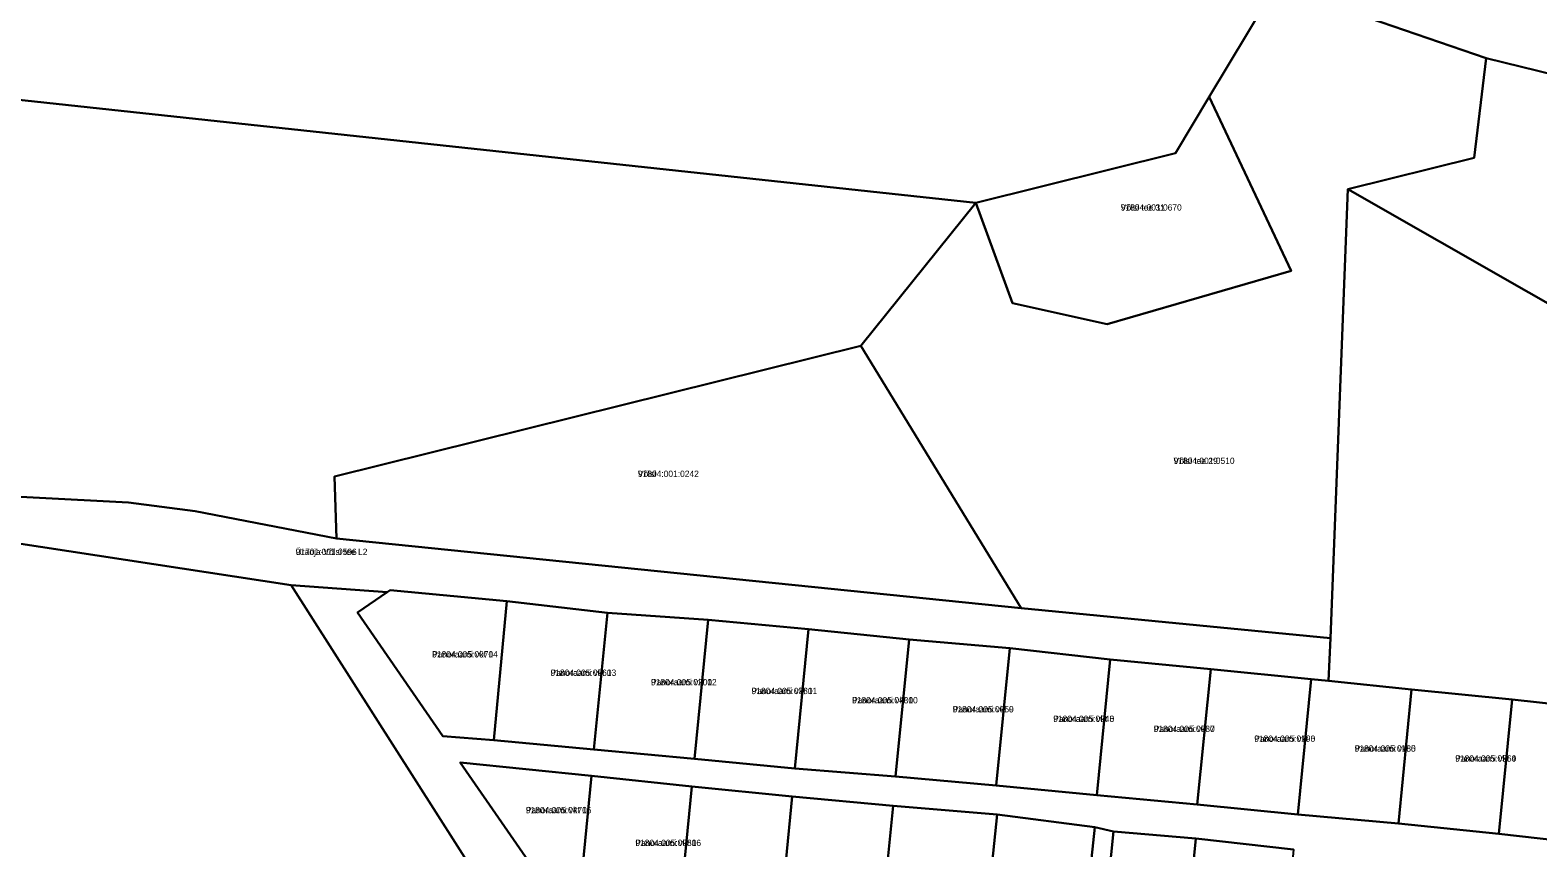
# Model space of a CAD drawing. Extents: x 655954 to 711923, y 6395079 to 6429745.
# Drawn here: x 676838.5 to 677196.9, y 6413724.6 to 6413918.9 of the extents above; entities that cross this region are included whole.
import ezdxf

# ---------------------------------------------------------------- set-up
doc = ezdxf.new("R2010")
doc.units = 0
for name, color, linetype in [('L_AADRESS', 7, 'Continuous'), ('PIIR', 7, 'Continuous'), ('TUNNUS', 7, 'Continuous')]:
    doc.layers.add(name, color=color, linetype=linetype)

msp = doc.modelspace()

# ---------------------------------------------------------------- linework, layer by layer
at = {"layer": 'PIIR'}
for points in [[(676618.85, 6413997.29), (676757.83, 6413982), (676748.25, 6413911.76), (677063.36, 6413877.89), (677036.02, 6413843.93), (676910.92, 6413812.85), (676911.36, 6413798.1), (676877.79, 6413804.6), (676861.95, 6413806.69), (676815, 6413809.12), (676760.41, 6413820.5), (676743.02, 6413822.9), (676724.12, 6413824.15), (676460.26, 6413781.02), (676439.86, 6413783.73), (676405.75, 6413788.28), (676399, 6413875.26), (676597.13, 6413862.25)], [(676757.83, 6413982), (676917.87, 6413963.45), (676991.22, 6413952.53), (677063.97, 6413940.17), (677132.61, 6413926), (677118.76, 6413903.06), (677110.76, 6413889.72), (677063.36, 6413877.89), (676748.25, 6413911.76)], [(677036.02, 6413843.93), (677063.36, 6413877.89), (677072.07, 6413854.02), (677094.58, 6413849.01), (677138.24, 6413861.74), (677118.76, 6413903.06), (677132.61, 6413926), (677134.69, 6413929.44), (677184.63, 6413912.26), (677181.78, 6413888.58), (677151.77, 6413881.11), (677147.6, 6413774.45), (677074.08, 6413781.56)], [(677151.77, 6413881.11), (677181.78, 6413888.58), (677184.63, 6413912.26), (677337.11, 6413874.84), (677343.16, 6413826.22), (677265.51, 6413773.16), (677238.84, 6413754.97), (677281.36, 6413807.1)], [(677063.36, 6413877.89), (677110.76, 6413889.72), (677118.76, 6413903.06), (677138.24, 6413861.74), (677094.58, 6413849.01), (677072.07, 6413854.02)], [(677147.6, 6413774.45), (677151.77, 6413881.11), (677281.36, 6413807.1), (677265.51, 6413773.16), (677256.27, 6413753.42), (677238.84, 6413754.97), (677214.64, 6413757.24), (677190.78, 6413759.81), (677166.9, 6413762.19), (677147.13, 6413764.24)], [(676910.92, 6413812.85), (677036.02, 6413843.93), (677074.08, 6413781.56), (676911.36, 6413798.1)], [(677147.6, 6413774.45), (677147.13, 6413764.24), (677143.03, 6413764.67), (677119.15, 6413767.07), (677095.25, 6413769.36), (677071.4, 6413772.06), (677047.47, 6413774.08), (677023.59, 6413776.53), (676999.69, 6413778.77), (676975.74, 6413780.46), (676951.83, 6413783.23), (676924.1, 6413785.82), (676923.38, 6413785.33), (676900.55, 6413787.01), (676722.83, 6413814.18), (676724.12, 6413824.15), (676743.02, 6413822.9), (676760.41, 6413820.5), (676815, 6413809.12), (676861.95, 6413806.69), (676877.79, 6413804.6), (676911.36, 6413798.1), (677074.08, 6413781.56)], [(676916.36, 6413780.5), (676923.38, 6413785.33), (676924.1, 6413785.82), (676951.83, 6413783.23), (676948.74, 6413750.14), (676936.62, 6413751.12)], [(676951.83, 6413783.23), (676975.74, 6413780.46), (676972.56, 6413747.96), (676948.74, 6413750.14)], [(676975.74, 6413780.46), (676999.69, 6413778.77), (676996.44, 6413745.72), (676972.56, 6413747.96)], [(676999.69, 6413778.77), (677023.59, 6413776.53), (677020.34, 6413743.47), (676996.44, 6413745.72)], [(677023.59, 6413776.53), (677047.47, 6413774.08), (677044.26, 6413741.54), (677020.34, 6413743.47)], [(677047.47, 6413774.08), (677071.4, 6413772.06), (677068.19, 6413739.43), (677044.26, 6413741.54)], [(677071.4, 6413772.06), (677095.25, 6413769.36), (677092.07, 6413737.13), (677068.19, 6413739.43)], [(677095.25, 6413769.36), (677119.15, 6413767.07), (677115.97, 6413734.87), (677092.07, 6413737.13)], [(677119.15, 6413767.07), (677143.03, 6413764.67), (677139.85, 6413732.51), (677115.97, 6413734.87)], [(677143.03, 6413764.67), (677147.13, 6413764.24), (677166.9, 6413762.19), (677163.76, 6413730.39), (677139.85, 6413732.51)], [(677166.9, 6413762.19), (677190.78, 6413759.81), (677187.63, 6413727.94), (677163.76, 6413730.39)], [(677190.78, 6413759.81), (677214.64, 6413757.24), (677211.48, 6413725.25), (677187.63, 6413727.94)], [(676963.98, 6413711.35), (676940.74, 6413744.84), (676971.97, 6413741.71), (676968.95, 6413710.82)], [(676968.95, 6413710.82), (676971.97, 6413741.71), (676995.85, 6413739.2), (676992.82, 6413708.35), (676985.56, 6413709.1)], [(676995.85, 6413739.2), (677019.7, 6413736.8), (677016.69, 6413705.72), (677001.51, 6413707.46), (676992.82, 6413708.35)], [(677040.59, 6413703.7), (677036.44, 6413704.17), (677018.82, 6413705.46), (677016.69, 6413705.72), (677019.7, 6413736.8), (677043.7, 6413734.54)], [(677043.7, 6413734.54), (677068.41, 6413732.49), (677065.16, 6413701.16), (677088.34, 6413698.99), (677076.26, 6413686.33), (677061.68, 6413701.52), (677040.59, 6413703.7)], [(677068.41, 6413732.49), (677091.65, 6413729.52), (677088.34, 6413698.99), (677065.16, 6413701.16)], [(677096.04, 6413728.43), (677092.88, 6413697.28), (677074.94, 6413677.09), (677075.6, 6413673.91), (677071.54, 6413668.9), (677053, 6413664.75), (677030.45, 6413659.62), (677007.01, 6413654.46), (676983.1, 6413649.39), (676959.15, 6413644.23), (676935.79, 6413639.38), (676913.44, 6413634.36), (676913.57, 6413640.66), (676950.06, 6413648.7), (676965.05, 6413651.99), (676981.14, 6413655.65), (676996.43, 6413659.58), (677012.12, 6413662.7), (677027.37, 6413665.74), (677043.95, 6413669.78), (677065.56, 6413675.12), (677076.26, 6413686.33), (677088.34, 6413698.99), (677091.65, 6413729.52)], [(677092.88, 6413697.28), (677096.04, 6413728.43), (677115.64, 6413726.84), (677112.86, 6413698.56), (677101.48, 6413690.21), (677102.75, 6413683.33), (677074.94, 6413677.09)], [(677112.88, 6413695.51), (677112.51, 6413685.52), (677102.75, 6413683.33), (677101.48, 6413690.21), (677112.86, 6413698.56), (677115.64, 6413726.84), (677138.84, 6413724.17), (677135.97, 6413693.58)]]:
    msp.add_lwpolyline(points, close=True, dxfattribs=at)
for points in [[(677789.14, 6413728.46), (677665.34, 6413764.41), (677639.35, 6413771.93), (677641.1, 6413778.01), (677587.87, 6413793.7), (677397.23, 6413855.41), (677337.11, 6413874.84), (677184.63, 6413912.26), (677134.69, 6413929.44), (677132.61, 6413926), (677063.97, 6413940.17), (676991.22, 6413952.53), (676917.87, 6413963.45), (676757.83, 6413982)], [(676722.83, 6413814.18), (676900.55, 6413787.01), (676949.83, 6413709.71), (676897.23, 6413654.7), (676920.56, 6413597.36), (676933.05, 6413555.27), (676946.82, 6413513.73), (676956.91, 6413480.43), (677002.62, 6413329.06), (677066.33, 6413319.15), (677231.27, 6413342.1), (677307.23, 6413354.1), (677309.72, 6413343.84), (677384.24, 6413366.61), (677380.25, 6413324.84), (677459.83, 6413354.2), (677597.5, 6413335.31), (677731.86, 6413311.49), (678085.04, 6413297.98), (678099.28, 6413215.93), (678143.84, 6412925.74)], [(676949.83, 6413709.71), (676900.55, 6413787.01), (676923.38, 6413785.33), (676916.36, 6413780.5), (676936.62, 6413751.12), (676948.74, 6413750.14), (676972.56, 6413747.96), (676996.44, 6413745.72), (677020.34, 6413743.47), (677044.26, 6413741.54), (677068.19, 6413739.43), (677092.07, 6413737.13), (677115.97, 6413734.87), (677139.85, 6413732.51), (677163.76, 6413730.39), (677187.63, 6413727.94), (677211.48, 6413725.25)], [(677138.84, 6413724.17), (677115.64, 6413726.84), (677096.04, 6413728.43), (677091.65, 6413729.52), (677068.41, 6413732.49), (677043.7, 6413734.54), (677019.7, 6413736.8), (676995.85, 6413739.2), (676971.97, 6413741.71), (676940.74, 6413744.84), (676963.98, 6413711.35)]]:
    msp.add_lwpolyline(points, dxfattribs=at)

# ---------------------------------------------------------------- texts
at = {"layer": 'L_AADRESS'}
for s, p in [('Võlsi tee 31', (677097.77, 6413876.04)), ('Võlsi tee 29', (677110.33, 6413815.83)), ('Võlsi', (676982.99, 6413812.74)), ('Üraoja-Võlsi tee L2', (676901.66, 6413794.19)), ('Panoraami vkt 14', (676934.09, 6413769.83)), ('Panoraami vkt 13', (676962.24, 6413765.46)), ('Panoraami vkt 12', (676986.12, 6413763.21)), ('Panoraami vkt 11', (677010.02, 6413761.12)), ('Panoraami vkt 10', (677033.91, 6413758.92)), ('Panoraami vkt 9', (677057.83, 6413756.77)), ('Panoraami vkt 8', (677081.72, 6413754.51)), ('Panoraami vkt 7', (677105.61, 6413752.11)), ('Panoraami vkt 6', (677129.5, 6413749.78)), ('Panoraami vkt 5', (677153.38, 6413747.45)), ('Panoraami vkt 4', (677177.27, 6413745.08)), ('Panoraami vkt 15', (676956.36, 6413732.81)), ('Panoraami vkt 16', (676982.4, 6413725.02))]:
    msp.add_text(s, height=1.5, dxfattribs=at).set_placement(p)
at = {"layer": 'TUNNUS'}
for s, p in [('91804:001:0670', (677097.77, 6413876.04)), ('91804:001:0510', (677110.33, 6413815.83)), ('91804:001:0242', (676982.99, 6413812.74)), ('91701:001:0596', (676901.66, 6413794.19)), ('91804:005:0070', (676934.09, 6413769.83)), ('91804:005:0060', (676962.24, 6413765.46)), ('91804:005:0200', (676986.12, 6413763.21)), ('91804:005:0380', (677010.02, 6413761.12)), ('91804:005:0430', (677033.91, 6413758.92)), ('91804:005:0050', (677057.83, 6413756.77)), ('91804:005:0040', (677081.72, 6413754.51)), ('91804:005:0030', (677105.61, 6413752.11)), ('91804:005:0190', (677129.5, 6413749.78)), ('91804:005:0180', (677153.38, 6413747.45)), ('91804:005:0560', (677177.27, 6413745.08)), ('91804:005:0470', (676956.36, 6413732.81)), ('91804:005:0080', (676982.4, 6413725.02))]:
    msp.add_text(s, height=1.5, dxfattribs=at).set_placement(p)

doc.saveas('drawing.dxf')
